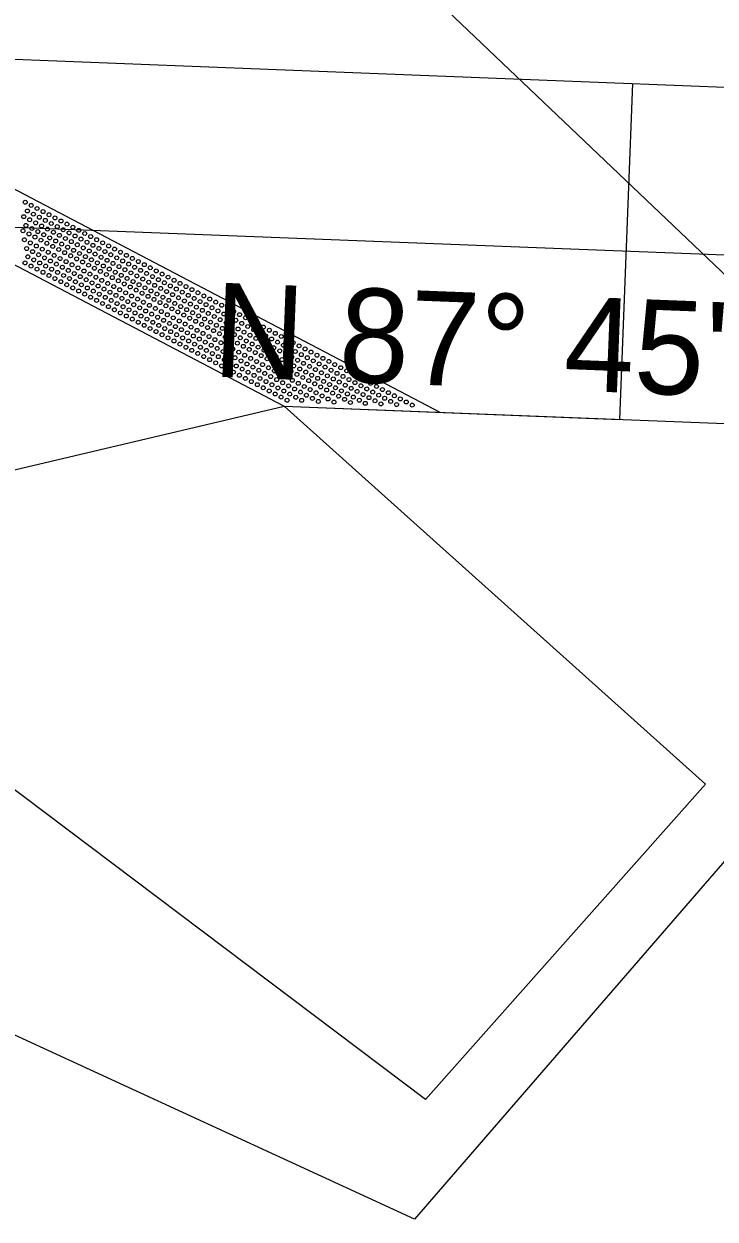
# Model space of a CAD drawing. Extents: x 2399886 to 2513208, y 556821 to 592417.
# Drawn here: x 2446034.84 to 2446055.41, y 557955.82 to 557991.37 of the extents above; entities that cross this region are included whole.
import ezdxf

# ---------------------------------------------------------------- set-up
doc = ezdxf.new("R2010")
doc.units = 0
for name, color, linetype in [('GM_X_City_Street_Text', 7, 'Continuous'), ('GM_X_Corporation', 7, 'Continuous'), ('GM_X_Interchange_Ramps', 7, 'Continuous'), ('GM_X_Interstate_Route', 7, 'Continuous'), ('GM_X_Interstate_Shield', 7, 'Continuous'), ('GM_X_Major_River', 7, 'Continuous'), ('GM_X_Major_River_Text', 7, 'Continuous'), ('GM_X_Section', 7, 'Continuous'), ('SH_Data', 7, 'Continuous')]:
    doc.layers.add(name, color=color, linetype=linetype)

msp = doc.modelspace()

# ---------------------------------------------------------------- linework, layer by layer
at = {"layer": 'GM_X_City_Street_Text'}
msp.add_line((2446026.606, 557990.629), (2446047.235, 557979.816), dxfattribs=at)
for centre in [(2446034.879, 557986.067), (2446034.945, 557985.806), (2446035.056, 557985.974), (2446035.233, 557985.881), (2446035.41, 557985.788), (2446034.834, 557985.639), (2446034.9, 557985.378), (2446035.011, 557985.546), (2446035.122, 557985.713), (2446035.188, 557985.453), (2446035.299, 557985.621), (2446035.476, 557985.528), (2446035.587, 557985.695), (2446035.653, 557985.435), (2446035.765, 557985.602), (2446035.942, 557985.51), (2446036.119, 557985.417), (2446034.813, 557985.218), (2446034.99, 557985.125), (2446035.077, 557985.286), (2446035.168, 557985.032), (2446035.254, 557985.193), (2446035.365, 557985.36), (2446035.431, 557985.1), (2446035.542, 557985.267), (2446035.719, 557985.175), (2446035.831, 557985.342), (2446035.897, 557985.082), (2446036.008, 557985.249), (2446036.185, 557985.156), (2446036.296, 557985.324), (2446036.362, 557985.064), (2446036.473, 557985.231), (2446036.65, 557985.138), (2446036.827, 557985.045), (2446034.854, 557984.95), (2446034.92, 557984.69), (2446035.032, 557984.858), (2446035.209, 557984.765), (2446035.345, 557984.939), (2446035.386, 557984.672), (2446035.522, 557984.846), (2446035.608, 557985.007), (2446035.699, 557984.753), (2446035.785, 557984.914), (2446035.876, 557984.661), (2446035.962, 557984.821), (2446036.074, 557984.989), (2446036.14, 557984.728), (2446036.251, 557984.896), (2446036.428, 557984.803), (2446036.539, 557984.971), (2446036.605, 557984.71), (2446036.716, 557984.878), (2446036.893, 557984.785), (2446037.005, 557984.953), (2446037.071, 557984.692), (2446037.182, 557984.86), (2446037.359, 557984.767), (2446037.536, 557984.674), (2446034.956, 557984.446), (2446035.098, 557984.597), (2446035.133, 557984.353), (2446035.275, 557984.504), (2446035.452, 557984.412), (2446035.563, 557984.579), (2446035.629, 557984.319), (2446035.74, 557984.486), (2446035.917, 557984.393), (2446036.053, 557984.568), (2446036.094, 557984.301), (2446036.23, 557984.475), (2446036.317, 557984.636), (2446036.408, 557984.382), (2446036.494, 557984.543), (2446036.671, 557984.45), (2446036.782, 557984.617), (2446036.848, 557984.357), (2446036.959, 557984.525), (2446037.137, 557984.432), (2446037.248, 557984.599), (2446037.314, 557984.339), (2446037.425, 557984.506), (2446037.602, 557984.414), (2446037.713, 557984.581), (2446037.779, 557984.321), (2446037.89, 557984.488), (2446038.067, 557984.395), (2446038.245, 557984.303), (2446034.875, 557984.262), (2446035.052, 557984.169), (2446035.23, 557984.076), (2446035.31, 557984.26), (2446035.407, 557983.984), (2446035.487, 557984.167), (2446035.664, 557984.074), (2446035.806, 557984.226), (2446035.842, 557983.981), (2446035.983, 557984.133), (2446036.16, 557984.04), (2446036.272, 557984.208), (2446036.338, 557983.947), (2446036.449, 557984.115), (2446036.585, 557984.289), (2446036.626, 557984.022), (2446036.762, 557984.196), (2446036.939, 557984.104), (2446037.025, 557984.264), (2446037.116, 557984.011), (2446037.202, 557984.171), (2446037.38, 557984.079), (2446037.491, 557984.246), (2446037.557, 557983.986), (2446037.668, 557984.153), (2446037.845, 557984.06), (2446037.956, 557984.228), (2446038.022, 557983.968), (2446038.133, 557984.135), (2446038.311, 557984.042), (2446038.422, 557984.21), (2446038.488, 557983.949), (2446038.599, 557984.117), (2446038.776, 557984.024), (2446035.584, 557983.891), (2446035.761, 557983.798), (2446035.938, 557983.705), (2446036.019, 557983.888), (2446036.115, 557983.612), (2446036.196, 557983.796), (2446036.373, 557983.703), (2446036.515, 557983.854), (2446036.55, 557983.61), (2446036.692, 557983.762), (2446036.803, 557983.929), (2446036.869, 557983.669), (2446036.98, 557983.836), (2446037.157, 557983.743), (2446037.293, 557983.918), (2446037.334, 557983.651), (2446037.47, 557983.825), (2446037.648, 557983.732), (2446037.734, 557983.893), (2446037.825, 557983.639), (2446037.911, 557983.8), (2446038.088, 557983.707), (2446038.199, 557983.875), (2446038.265, 557983.614), (2446038.377, 557983.782), (2446038.554, 557983.689), (2446038.665, 557983.857), (2446038.731, 557983.596), (2446038.842, 557983.764), (2446038.953, 557983.931), (2446039.019, 557983.671), (2446039.13, 557983.838), (2446039.307, 557983.746), (2446039.485, 557983.653), (2446036.292, 557983.519), (2446036.47, 557983.427), (2446036.647, 557983.334), (2446036.727, 557983.517), (2446036.824, 557983.241), (2446036.904, 557983.424), (2446037.046, 557983.576), (2446037.082, 557983.331), (2446037.223, 557983.483), (2446037.259, 557983.239), (2446037.4, 557983.39), (2446037.512, 557983.558), (2446037.578, 557983.297), (2446037.689, 557983.465), (2446037.866, 557983.372), (2446038.002, 557983.546), (2446038.043, 557983.279), (2446038.179, 557983.454), (2446038.356, 557983.361), (2446038.442, 557983.521), (2446038.533, 557983.268), (2446038.62, 557983.429), (2446038.797, 557983.336), (2446038.908, 557983.503), (2446038.974, 557983.243), (2446039.085, 557983.41), (2446039.196, 557983.578), (2446039.262, 557983.318), (2446039.373, 557983.485), (2446039.551, 557983.392), (2446039.662, 557983.56), (2446039.728, 557983.299), (2446039.839, 557983.467), (2446040.016, 557983.374), (2446040.193, 557983.281), (2446037.001, 557983.148), (2446037.178, 557983.055), (2446037.355, 557982.962), (2446037.436, 557983.146), (2446037.613, 557983.053), (2446037.755, 557983.205), (2446037.79, 557982.96), (2446037.932, 557983.112), (2446038.109, 557983.019), (2446038.22, 557983.186), (2446038.286, 557982.926), (2446038.397, 557983.094), (2446038.574, 557983.001), (2446038.71, 557983.175), (2446038.752, 557982.908), (2446038.888, 557983.082), (2446039.065, 557982.989), (2446039.151, 557983.15), (2446039.242, 557982.897), (2446039.328, 557983.057), (2446039.439, 557983.225), (2446039.505, 557982.964), (2446039.617, 557983.132), (2446039.794, 557983.039), (2446039.905, 557983.207), (2446039.971, 557982.946), (2446040.082, 557983.114), (2446040.259, 557983.021), (2446040.37, 557983.188), (2446040.436, 557982.928), (2446040.547, 557983.096), (2446040.725, 557983.003), (2446040.902, 557982.91), (2446037.532, 557982.869), (2446037.71, 557982.777), (2446037.887, 557982.684), (2446037.967, 557982.867), (2446038.064, 557982.591), (2446038.144, 557982.774), (2446038.322, 557982.681), (2446038.463, 557982.833), (2446038.499, 557982.589), (2446038.64, 557982.74), (2446038.818, 557982.647), (2446038.929, 557982.815), (2446038.995, 557982.555), (2446039.106, 557982.722), (2446039.283, 557982.629), (2446039.419, 557982.804), (2446039.46, 557982.536), (2446039.596, 557982.711), (2446039.682, 557982.872), (2446039.773, 557982.618), (2446039.86, 557982.779), (2446039.95, 557982.525), (2446040.037, 557982.686), (2446040.148, 557982.853), (2446040.214, 557982.593), (2446040.325, 557982.761), (2446040.502, 557982.668), (2446040.613, 557982.835), (2446040.679, 557982.575), (2446040.791, 557982.742), (2446040.968, 557982.65), (2446041.079, 557982.817), (2446041.145, 557982.557), (2446041.256, 557982.724), (2446041.433, 557982.631), (2446041.61, 557982.539), (2446038.241, 557982.498), (2446038.418, 557982.405), (2446038.595, 557982.312), (2446038.676, 557982.496), (2446038.772, 557982.22), (2446038.853, 557982.403), (2446039.03, 557982.31), (2446039.172, 557982.462), (2446039.207, 557982.217), (2446039.349, 557982.369), (2446039.526, 557982.276), (2446039.637, 557982.444), (2446039.703, 557982.183), (2446039.814, 557982.351), (2446039.992, 557982.258), (2446040.128, 557982.432), (2446040.169, 557982.165), (2446040.305, 557982.339), (2446040.391, 557982.5), (2446040.482, 557982.247), (2446040.568, 557982.407), (2446040.745, 557982.314), (2446040.857, 557982.482), (2446040.922, 557982.222), (2446041.034, 557982.389), (2446041.211, 557982.296), (2446041.322, 557982.464), (2446041.388, 557982.203), (2446041.499, 557982.371), (2446041.676, 557982.278), (2446041.787, 557982.446), (2446041.853, 557982.185), (2446041.965, 557982.353), (2446042.142, 557982.26), (2446042.319, 557982.167), (2446038.95, 557982.127), (2446039.127, 557982.034), (2446039.304, 557981.941), (2446039.384, 557982.124), (2446039.481, 557981.848), (2446039.562, 557982.032), (2446039.739, 557981.939), (2446039.88, 557982.09), (2446039.916, 557981.846), (2446040.058, 557981.998), (2446040.235, 557981.905), (2446040.346, 557982.072), (2446040.412, 557981.812), (2446040.523, 557981.979), (2446040.659, 557982.154), (2446040.7, 557981.887), (2446040.836, 557982.061), (2446041.013, 557981.968), (2446041.1, 557982.129), (2446041.19, 557981.875), (2446041.277, 557982.036), (2446041.454, 557981.943), (2446041.565, 557982.111), (2446041.631, 557981.85), (2446041.742, 557982.018), (2446041.919, 557981.925), (2446042.031, 557982.092), (2446042.097, 557981.832), (2446042.208, 557982), (2446042.385, 557981.907), (2446042.496, 557982.074), (2446042.562, 557981.814), (2446042.673, 557981.981), (2446042.85, 557981.889), (2446039.658, 557981.755), (2446039.835, 557981.662), (2446040.012, 557981.57), (2446040.093, 557981.753), (2446040.19, 557981.477), (2446040.27, 557981.66), (2446040.447, 557981.567), (2446040.589, 557981.719), (2446040.624, 557981.474), (2446040.766, 557981.626), (2446040.877, 557981.794), (2446040.943, 557981.533), (2446041.054, 557981.701), (2446041.232, 557981.608), (2446041.368, 557981.782), (2446041.409, 557981.515), (2446041.545, 557981.69), (2446041.722, 557981.597), (2446041.808, 557981.757), (2446041.899, 557981.504), (2446041.985, 557981.665), (2446042.162, 557981.572), (2446042.274, 557981.739), (2446042.34, 557981.479), (2446042.451, 557981.646), (2446042.628, 557981.554), (2446042.739, 557981.721), (2446042.805, 557981.461), (2446042.916, 557981.628), (2446043.027, 557981.796), (2446043.093, 557981.535), (2446043.205, 557981.703), (2446043.382, 557981.61), (2446043.559, 557981.517), (2446040.367, 557981.384), (2446040.544, 557981.291), (2446040.721, 557981.198), (2446040.802, 557981.382), (2446040.898, 557981.105), (2446040.979, 557981.289), (2446041.12, 557981.44), (2446041.156, 557981.196), (2446041.298, 557981.348), (2446041.333, 557981.103), (2446041.475, 557981.255), (2446041.586, 557981.422), (2446041.652, 557981.162), (2446041.763, 557981.329), (2446041.94, 557981.237), (2446042.076, 557981.411), (2446042.117, 557981.144), (2446042.253, 557981.318), (2446042.43, 557981.225), (2446042.517, 557981.386), (2446042.608, 557981.132), (2446042.694, 557981.293), (2446042.871, 557981.2), (2446042.982, 557981.368), (2446043.048, 557981.107), (2446043.159, 557981.275), (2446043.271, 557981.443), (2446043.337, 557981.182), (2446043.448, 557981.35), (2446043.625, 557981.257), (2446043.736, 557981.424), (2446043.802, 557981.164), (2446043.913, 557981.332), (2446044.09, 557981.239), (2446044.267, 557981.146), (2446041.075, 557981.013), (2446041.252, 557980.92), (2446041.43, 557980.827), (2446041.51, 557981.01), (2446041.687, 557980.917), (2446041.829, 557981.069), (2446041.864, 557980.825), (2446042.006, 557980.976), (2446042.183, 557980.883), (2446042.294, 557981.051), (2446042.36, 557980.791), (2446042.472, 557980.958), (2446042.649, 557980.865), (2446042.785, 557981.04), (2446042.826, 557980.772), (2446042.962, 557980.947), (2446043.139, 557980.854), (2446043.225, 557981.015), (2446043.316, 557980.761), (2446043.402, 557980.922), (2446043.514, 557981.089), (2446043.58, 557980.829), (2446043.691, 557980.996), (2446043.868, 557980.904), (2446043.979, 557981.071), (2446044.045, 557980.811), (2446044.156, 557980.978), (2446044.333, 557980.885), (2446044.445, 557981.053), (2446044.511, 557980.793), (2446044.622, 557980.96), (2446044.799, 557980.867), (2446044.976, 557980.774), (2446041.607, 557980.734), (2446041.784, 557980.641), (2446041.961, 557980.548), (2446042.042, 557980.732), (2446042.138, 557980.455), (2446042.219, 557980.639), (2446042.396, 557980.546), (2446042.538, 557980.698), (2446042.573, 557980.453), (2446042.715, 557980.605), (2446042.892, 557980.512), (2446043.003, 557980.68), (2446043.069, 557980.419), (2446043.18, 557980.587), (2446043.357, 557980.494), (2446043.493, 557980.668), (2446043.534, 557980.401), (2446043.67, 557980.575), (2446043.757, 557980.736), (2446043.848, 557980.483), (2446043.934, 557980.643), (2446044.025, 557980.39), (2446044.111, 557980.55), (2446044.222, 557980.718), (2446044.288, 557980.458), (2446044.399, 557980.625), (2446044.577, 557980.532), (2446044.688, 557980.7), (2446044.754, 557980.439), (2446044.865, 557980.607), (2446045.042, 557980.514), (2446045.153, 557980.682), (2446045.219, 557980.421), (2446045.33, 557980.589), (2446045.507, 557980.496), (2446045.685, 557980.403), (2446042.315, 557980.363), (2446042.492, 557980.27), (2446042.67, 557980.177), (2446042.75, 557980.36), (2446042.927, 557980.267), (2446043.104, 557980.175), (2446043.246, 557980.326), (2446043.423, 557980.233), (2446043.6, 557980.141), (2446043.712, 557980.308), (2446043.889, 557980.215), (2446044.066, 557980.122), (2446044.202, 557980.297), (2446044.379, 557980.204), (2446044.465, 557980.365), (2446044.556, 557980.111), (2446044.642, 557980.272), (2446044.82, 557980.179), (2446044.931, 557980.347), (2446044.997, 557980.086), (2446045.108, 557980.254), (2446045.285, 557980.161), (2446045.396, 557980.328), (2446045.462, 557980.068), (2446045.573, 557980.236), (2446045.751, 557980.143), (2446045.862, 557980.31), (2446045.928, 557980.05), (2446046.039, 557980.217), (2446046.216, 557980.125), (2446046.393, 557980.032)]:
    msp.add_circle(centre, 0.0585, dxfattribs=at)
at = {"layer": 'GM_X_Corporation'}
msp.add_line((2446023.438, 557975.479), (2446042.58, 557979.998), dxfattribs=at)
at = {"layer": 'GM_X_Interchange_Ramps'}
for p, q in [((2446046.458, 557955.821), (2446019.289, 557968.316)), ((2446057.107, 557968.113), (2446046.458, 557955.821))]:
    msp.add_line(p, q, dxfattribs=at)
at = {"layer": 'GM_X_Interstate_Route'}
msp.add_line((2446052.573, 557979.608), (2446052.962, 557989.601), dxfattribs=at)
at = {"layer": 'GM_X_Interstate_Shield'}
msp.add_lwpolyline([(2446042.58, 557979.998), (2446055.115, 557968.758), (2446046.789, 557959.375), (2446034.143, 557968.902), (2446023.438, 557975.479)], dxfattribs=at)
at = {"layer": 'GM_X_Major_River'}
msp.add_line((2446090.916, 557983.117), (2446022.862, 557985.771), dxfattribs=at)
at = {"layer": 'GM_X_Major_River_Text'}
for p, q in [((2446044.577, 557994.506), (2446076.349, 557964.231)), ((2446042.58, 557979.998), (2446052.573, 557979.608))]:
    msp.add_line(p, q, dxfattribs=at)
at = {"layer": 'GM_X_Section'}
for p, q in [((2446021.951, 557990.81), (2446091.111, 557988.113)), ((2446021.951, 557990.81), (2446042.58, 557979.998)), ((2446042.58, 557979.998), (2446090.721, 557978.12))]:
    msp.add_line(p, q, dxfattribs=at)
at = {"layer": 'SH_Data'}
msp.add_line((2446090.916, 557983.117), (2446022.862, 557985.771), dxfattribs=at)

# ---------------------------------------------------------------- texts
msp.add_text('N 87%%d 45\' 59" W', height=2.8, rotation=357.7664, dxfattribs=at).set_placement((2446040.436, 557980.882))

doc.saveas('drawing.dxf')
